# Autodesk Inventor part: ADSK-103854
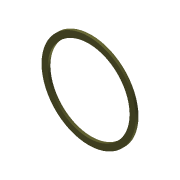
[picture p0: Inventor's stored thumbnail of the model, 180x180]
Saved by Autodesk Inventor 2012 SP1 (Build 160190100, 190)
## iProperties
Shininess: 25.0
Created: 2001-04
Part Number: ADSK-103854
Document SubType Name: Modeling
Designer: Administrator
Stock Number: ADSK-103854
Density: 1 g/cm^3
Material: Default
Density: 0.0
Volumn: 0.0
Area: 0.0
PropertySet Name: Model Information
Control State: 0
Master: False
Checked Out: False
Author: Administrator
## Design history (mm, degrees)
sketch "Sketch1"
  geometry: C1 r 26.988 at (0, 0); C2 r 23.495 at (0, 0)
  constraints: 2 centre point
  dimensions: "d0" = 46.99 diameter of C2; "d1" = 53.975 diameter of C1
extrude "Extrusion1" new body sketch "Sketch1" distance "d2" = 1.5748; taper "d3" = 0 deg
body "Solid1"
